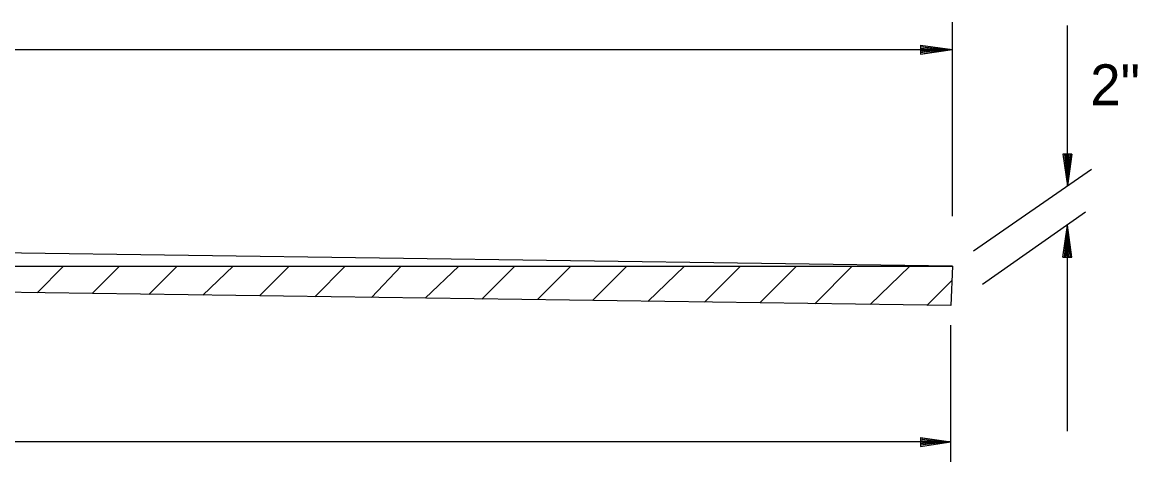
# Model space of a CAD drawing. Extents: x 1373918 to 1374069, y 381000 to 381245.
# Drawn here: x 1374003.52 to 1374019.88, y 381171.43 to 381177.87 of the extents above; entities that cross this region are included whole.
import ezdxf

# ---------------------------------------------------------------- set-up
doc = ezdxf.new("R2010")
doc.units = 0
doc.layers.add('Default', color=7, linetype='Continuous')

msp = doc.modelspace()

# ---------------------------------------------------------------- linework, layer by layer
at = {"layer": 'Default'}
for p, q in [((1374017.161, 381175.031), (1374017.161, 381177.873)), ((1374018.847, 381175.474), (1374018.847, 381177.828)), ((1373976.005, 381177.474), (1374017.161, 381177.474)), ((1374016.693, 381177.54), (1374017.161, 381177.474)), ((1374016.693, 381177.54), (1374016.693, 381177.407)), ((1374016.693, 381177.519), (1374017.005, 381177.474)), ((1374016.693, 381177.519), (1374017.07, 381177.474)), ((1374016.693, 381177.496), (1374016.849, 381177.474)), ((1374016.693, 381177.496), (1374016.917, 381177.474)), ((1374016.693, 381177.407), (1374017.161, 381177.474)), ((1374016.693, 381177.452), (1374016.849, 381177.474)), ((1374016.693, 381177.43), (1374017.005, 381177.474)), ((1374016.693, 381177.407), (1374017.07, 381177.474)), ((1374016.693, 381177.43), (1374016.917, 381177.474)), ((1374016.693, 381177.452), (1374016.761, 381177.474)), ((1374016.693, 381177.474), (1374016.761, 381177.474)), ((1374018.782, 381175.941), (1374018.847, 381175.474)), ((1374018.914, 381175.941), (1374018.782, 381175.941)), ((1374018.804, 381175.941), (1374018.847, 381175.63)), ((1374018.804, 381175.941), (1374018.847, 381175.564)), ((1374018.825, 381175.941), (1374018.847, 381175.786)), ((1374018.825, 381175.941), (1374018.847, 381175.719)), ((1374018.914, 381175.941), (1374018.847, 381175.474)), ((1374018.87, 381175.941), (1374018.847, 381175.786)), ((1374018.893, 381175.941), (1374018.847, 381175.63)), ((1374018.914, 381175.941), (1374018.847, 381175.564)), ((1374018.893, 381175.941), (1374018.847, 381175.719)), ((1374018.847, 381175.941), (1374018.847, 381175.874)), ((1374018.87, 381175.941), (1374018.847, 381175.874)), ((1374017.471, 381174.521), (1374019.203, 381175.719)), ((1374017.604, 381174.032), (1374019.115, 381175.097)), ((1374017.161, 381174.298), (1373976.005, 381174.875)), ((1374018.782, 381174.431), (1374018.847, 381174.898)), ((1374018.804, 381174.431), (1374018.847, 381174.831)), ((1374018.847, 381171.877), (1374018.847, 381174.898)), ((1374018.914, 381174.431), (1374018.847, 381174.898)), ((1374018.914, 381174.431), (1374018.847, 381174.831)), ((1374018.804, 381174.431), (1374018.847, 381174.742)), ((1374018.825, 381174.431), (1374018.847, 381174.675)), ((1374018.893, 381174.431), (1374018.847, 381174.742)), ((1374018.893, 381174.431), (1374018.847, 381174.675)), ((1374018.825, 381174.431), (1374018.847, 381174.586)), ((1374018.87, 381174.431), (1374018.847, 381174.586)), ((1374018.87, 381174.431), (1374018.847, 381174.521)), ((1374018.847, 381174.431), (1374018.847, 381174.521)), ((1374018.782, 381174.431), (1374018.914, 381174.431)), ((1373964.457, 381174.297), (1374017.161, 381174.297)), ((1374017.138, 381173.72), (1373976.005, 381174.298)), ((1374003.735, 381173.908), (1374004.123, 381174.298)), ((1374004.544, 381173.897), (1374004.944, 381174.298)), ((1374005.376, 381173.885), (1374005.788, 381174.298)), ((1374006.166, 381173.874), (1374006.611, 381174.298)), ((1374006.998, 381173.863), (1374007.432, 381174.298)), ((1374007.809, 381173.851), (1374008.253, 381174.298)), ((1374008.64, 381173.84), (1374009.077, 381174.298)), ((1374009.427, 381173.828), (1374009.92, 381174.298)), ((1374010.26, 381173.816), (1374010.742, 381174.298)), ((1374011.075, 381173.809), (1374011.563, 381174.298)), ((1374011.882, 381173.794), (1374012.385, 381174.298)), ((1374012.691, 381173.782), (1374013.229, 381174.298)), ((1374013.523, 381173.771), (1374014.051, 381174.298)), ((1374014.334, 381173.759), (1374014.873, 381174.298)), ((1374015.145, 381173.747), (1374015.693, 381174.298)), ((1374015.955, 381173.737), (1374016.538, 381174.298)), ((1374017.161, 381174.298), (1374017.138, 381173.72)), ((1374016.787, 381173.724), (1374017.152, 381174.089)), ((1374017.138, 381171.432), (1374017.138, 381173.431)), ((1374017.138, 381171.722), (1373976.005, 381171.722)), ((1374016.693, 381171.787), (1374017.138, 381171.722)), ((1374016.693, 381171.787), (1374017.07, 381171.722)), ((1374016.693, 381171.787), (1374016.693, 381171.655)), ((1374016.693, 381171.767), (1374016.982, 381171.722)), ((1374016.693, 381171.767), (1374016.917, 381171.722)), ((1374016.693, 381171.743), (1374016.828, 381171.722)), ((1374016.693, 381171.743), (1374016.761, 381171.722)), ((1374016.693, 381171.655), (1374017.138, 381171.722)), ((1374016.693, 381171.699), (1374016.828, 381171.722)), ((1374016.693, 381171.677), (1374016.982, 381171.722)), ((1374016.693, 381171.677), (1374017.07, 381171.722)), ((1374016.693, 381171.699), (1374016.917, 381171.722)), ((1374016.693, 381171.722), (1374016.761, 381171.722))]:
    msp.add_line(p, q, dxfattribs=at)

# ---------------------------------------------------------------- texts
msp.add_text('2"', height=0.6, dxfattribs=at).set_placement((1374019.182, 381176.657))

doc.saveas('drawing.dxf')
